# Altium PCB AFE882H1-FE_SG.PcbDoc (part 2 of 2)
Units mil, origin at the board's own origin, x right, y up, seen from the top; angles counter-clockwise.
Board outline 2755.91 x 1181.1 mil, 4 copper layers (Top Layer, Int1 (GND), Int2 (PWR), Bottom Layer), stack 53.912 mil thick; 101 components, 57 nets, 291 pads, 95 vias.
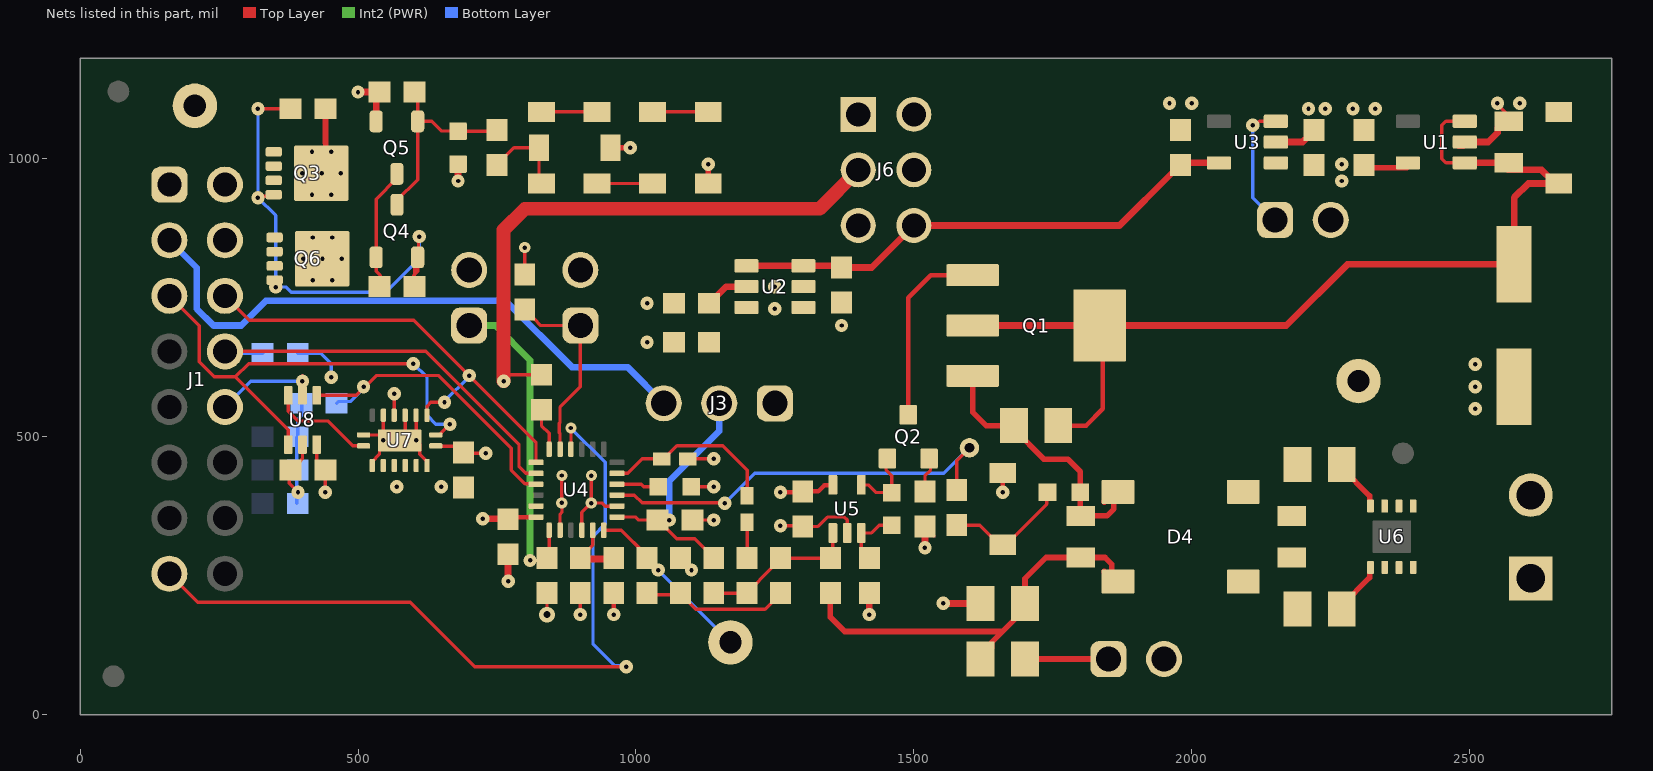
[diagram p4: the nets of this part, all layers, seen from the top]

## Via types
v1: diameter 24, hole 8, Top Layer to Bottom Layer, tented both sides, 65 vias
v2: diameter 19.68, hole 7.87, Top Layer to Bottom Layer, 16 vias
v3: diameter 20, hole 8, Top Layer to Bottom Layer, tented both sides, 9 vias
v4: diameter 19.68, hole 7.87, Top Layer to Bottom Layer, tented both sides, 4 vias
v5: diameter 28, hole 12, Top Layer to Bottom Layer, tented both sides, 1 vias

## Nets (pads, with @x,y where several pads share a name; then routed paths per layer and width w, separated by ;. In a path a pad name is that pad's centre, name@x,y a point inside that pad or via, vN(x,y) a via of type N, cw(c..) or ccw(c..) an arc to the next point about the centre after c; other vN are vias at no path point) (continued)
GND: C2.2 C3.2 C4.2 C5.1 C6.2 C9.2 C10.2 C11.2 C12.2 C13.2 C15.2 C16.2 C18.1 C19.2 C20.2 C21.2 C22.1 C24.2 C25.2 D2.2 J1.1 J8.2 Q5.2 R3.2 R4.1 R9.1 R13.2 R20.1 TP3.1 TP4.1 U1.2 U2.1 U2.2 U3.2 U4.14 U4.16 U4.20 U5.2 U7.3 U7.4 U7.6 U7.8 U7.10 U7.11 U7.12 U7.13 U7.14 U7.15 U7.17 U8.3 | length 1649.5
  Top Layer w6: U8.3@425.59,485.71 425.59,455.7 C25.2@441.29,440 ; v1(441.29,400) 441.29,439.8 C25.2@441.5,440 C25.2@450,440 ; U7.8@510.04,503.13 538.63,503.13 U7.17@545.47,496.29 ; U7.10@525.79,448.01 525.79,455.1 538.63,467.94 538.63,486.44 v4(545.47,493.29) U7.17@545.47,496.29 ; U7.6@544.9,539.13 U7.6@545.47,538.56 U7.17@545.47,496.29 ; U7.17@575,493.29 584.84,503.13 U7.4@584.84,538.56 ; U7.3@604.53,538.56 v4(604.53,493.29) 611.37,486.44 611.37,467.94 624.21,455.1 U7.15@624.21,448.01 ; R3.2@800,791.5 v3(800,840) ; v5(840,180) C12.2@840,222.44 ; U4.14@863.46,331.72 863.46,360.14 866.93,363.61 866.93,380.67 v3(866.6,381) ; v3@863.46,377.85 v3(866.6,381) ; v3(866.93,430.19) 866.6,429.86 v3(866.6,381) ; v1(900,180) C11.2@900,218.5 900,217.52 C11.2@915.7,201.82 ; U4.16@902.83,331.72 902.83,363.65 v3@919.18,380 ; v3(919.74,429.89) 919.7,429.85 v3(919.7,380.52) ; v3@920,380 v3@919.18,380 ; U4.20@965.82,375.03 945.02,375.03 942.22,377.83 939.52,380.52 v3(919.7,380.52) ; C6.2@1068.51,740 C6.2@1075.28,733.23 ; C2.2@1070.47,663.3 C2.2@1070.47,670 ; C15.2@1080,281.5 1100,261.5 v1(1100,260) ; C18.1@1093.62,460 v1(1140,460) ; C13.2@1101.49,350 v1(1140,350) ; C16.2@1103.41,408.09 1101.5,410 v1(1140,410) ; v1(1260,340) 1298.51,340 C9.2@1300,338.51 1327.7,338.51 1344.53,355.34 1374.87,355.34 1380,350.21 U5.2@1380,326.69 ; R9.1@1520,338.5 1520,337.52 R9.1@1535.7,321.82 ; U1.2@2479.68,1020.88 U1.2@2489.52,1020.88 ; v1@2556.6,1090.97 C5.1@2568.24,1079.33 ; v3@919.18,380 v3(919.7,380.52)
  Top Layer w12: v1(500,1120) R20.1@538.5,1120 ; Q5.2@532.6,1067.24 532.6,1112.6 R20.1@539.25,1119.25 ; v1(680,960) C22.1@680,990.47 ; v1(770,240) C10.2@770,288.5 ; v1(1420,180) R4.1@1420,216.54 ; v1(1520,300) R9.1@1520,338.5 ; v1(1553.21,200) R13.2@1602.91,200 ; U3.2@2151.18,1030 2199.49,1030 2209.49,1040 C19.2@2230,1040 ; U1.2@2491.18,1030 2533.5,1030 2550.41,1046.91 2550.41,1055.68 2554.72,1060 C5.1@2570,1060
  other v1: 570,410 650,410 2510,550 2510,590 2510,630 1020,670 1370,700 1250,730 1020,740 1250,770 2210,1090 2240,1090 2290,1090 2330,1090 1960,1100 2000,1100 2550,1100 2590,1100
ID0: J1.5 U7.1 U8.1 | length 893.4
  Top Layer w6: J1.5@160.52,753.39 214.65,699.27 214.65,634.39 241.52,607.52 279.53,607.52 ; U8.1@374.41,485.71 374.41,512.63 279.53,607.52 ; v1(599.61,631.33) 303.34,631.33 279.53,607.52 ; U7.1@639.96,503.13 647.05,503.13 650,506.08 650,507.25 v1(665.36,522.62)
  Bottom Layer w6: v1(599.61,631.33) 624.21,606.72 624.21,538.56 640.16,522.62 v1(665.36,522.62)
IOVDD: C10.1 C24.1 C25.1 J6.3 R8.2 R10.2 R12.2 R15.2 R16.2 R21.2 U4.12 U7.5 U7.16 U8.2 | length 1635.4
  Top Layer w6: C25.1@378.5,440 376.22,437.71 376.22,415.81 v1(392.03,400) ; C25.1@380,440.51 395.19,455.7 395.7,455.7 400,460 U8.2@400,485.71 ; U7.5@565.16,538.56 v1(565.16,577.01) ; U7.16@639.96,483.44 640.42,482.99 C24.1@690,482.99 ; C24.1@690,471.5 691.5,470 v1(730,470) ; v1(724.17,352.59) v1@725.26,351.5 ; v1(762.1,600) 773.6,611.5 R8.2@830,611.5
  Top Layer w8: C10.1@770,360 774.66,355.34 U4.12@820.15,355.34
  Top Layer w12: v1(724.17,352.59) 767.41,352.59 C10.1@770,350
  Top Layer w25: v1(762.1,600) 762.1,872.1 800,910 1330,910 J6.3@1400,980
  Bottom Layer w6: R16.2@390,380 390,397.97 v1(392.03,400) ; v1@390,400 390,498.5 R21.2@391.5,500 391.5,531.55 398.5,538.56 R12.2@398.5,560 ; R10.2@391.5,650 433.06,650 451.73,631.33 v1(451.73,606.72)
LOOP+: C1.2 C8.2 D4.1 Q1.3 R2.2 | length 506.1
  Top Layer w10: Q1.3@1605.83,609.45 1605.83,544.17 1630,520 R2.2@1670,520 ; R2.2@1680,520 1680,513.5 1734.07,459.43 1777.02,459.43 1799.53,436.92 C1.2@1799.53,400 1799.53,367.87 C8.2@1805,362.4 ; C8.2@1800,357.4 1847.4,357.4 1859.91,369.91 1859.91,393.22 D4.1@1867.4,400.71 1859.53,400.71 1842.87,384.05 D4.1@1842.87,382.4
LOOP-: C8.1 D4.4 R13.1 R14.1 R23.1 | length 790.3
  Top Layer w10: R14.1@1350,218.5 1350,175.17 1375.72,149.45 1659.45,149.45 ; R23.1@1620,100 1640,120 1640,130 1659.45,149.45 ; R13.1@1711.18,205.9 R13.1@1717.09,200 ; R13.1@1720,210 R13.1@1720,213.74 ; D4.4@1842.87,257.6 1842.87,255.95 1856.5,242.32 D4.4@1860,242.32 ; D4.4@1867.4,239.29 1856.41,250.28 1856.41,270.09 1843.9,282.6 C8.1@1800,282.6 1738.07,282.6 1700,244.53 R13.1@1700,200 1680,180 1680,170 1659.45,149.45
MOD_IN: R1.1 TP1.1 U4.21 | length 767.3
  Top Layer w6: U4.21@965.82,394.71 997.36,394.71 1011.07,381 1159,381 v1(1160,380) ; R1.1@1577.06,403.89 1577.06,457.06 TP1.1@1600,480
  Bottom Layer w6: v1(1160,380) 1214.08,434.08 1554.08,434.08 TP1.1@1600,480
NetC1_1: C1.1 D1.2 R1.2 | length 227.1
  Top Layer w6: R1.2@1577.06,340.9 1618.63,340.9 1649.53,310 D1.2@1660,310 ; D1.2@1660,305.53 1666,305.53 1739.24,378.77 1739.24,398.76 C1.1@1740.47,400
NetC2_1: C2.1 J3.1 U2.6
NetC5_2: C5.2 C21.1 D2.1 Q1.2 Q1.4 R2.1 U1.1 U1.3 | length 1771.9
  Top Layer w6: U1.1@2491.18,992.6 2457.4,992.6 2450,1000 2450,1060 2457.4,1067.4 U1.3@2491.18,1067.4
  Top Layer w8: R2.1@1760,520 1810,520 1840,550 1840,690 Q1.4@1850,700
  Top Layer w12: Q1.2@1605.83,700 Q1.4@1830,700 ; Q1.4@1834.17,700 1850,700 2170,700 2280,810 C21.1@2570,810 ; U1.1@2500.51,992.6 C5.2@2570,992.6 ; C5.2@2567.4,982.6 2570,980 2629.53,980 D2.1@2649.53,960 ; C21.1@2580,810.24 2580,930 2605.53,955.53 2649.53,955.53 D2.1@2660,955.53
NetC6_1: C6.1 U2.5 | length 101.8
  Top Layer w6: C6.1@1125.27,754.63 1135.7,744.2 1136.19,743.71 C6.1@1139.32,740.58 ; C6.1@1130.51,740 C6.1@1131.5,740
  Top Layer w12: C6.1@1131.5,740 1132.48,740 1162.48,770 U2.5@1200,770
NetC7_1: C7.1 R4.2 U5.3 | length 111.3
  Top Layer w6: R4.2@1420,281.5 1405.59,295.91 U5.3@1405.59,326.69 1423.9,326.69 1437.68,340.47 C7.1@1460,340.47
NetC7_2: C7.2 Q2.1 U5.4 | length 126.4
  Top Layer w6: U5.4@1405.59,413.31 1405.86,413.04 1418.95,413.04 1432.46,399.53 C7.2@1460,399.53 1460,430 1450,440 1450,458.03 Q2.1@1452.6,460.63
NetC11_1: C11.1 R22.2 U4.17 | length 107.5
  Top Layer w6: C11.1@900,281.49 C11.1@901.49,280 ; C11.1@910,290 910,292.48 922.51,304.99 U4.17@922.51,331.72
  Top Layer w12: C11.1@901.49,280 R22.2@960,280
NetC14_1: C14.1 D4.2 FB2.1
NetC14_2: C14.2 D4.3 FB1.1
NetC15_1: C15.1 R6.1 R7.1 | length 273.2
  Top Layer w6: R6.1@1020,215.48 1076.98,215.48 C15.1@1080,218.5 ; R6.1@1024.09,228.83 R6.1@1030.08,228.83 ; C15.1@1080,219.49 C15.1@1080,218.5 ; R7.1@1260,218.5 1260,217.52 1232.25,189.77 1107.75,189.77 1080,217.52 C15.1@1080,218.5
NetC16_1: C16.1 U4.22 | length 76.5
  Top Layer w6: U4.22@965.82,414.4 1009.37,414.4 1013.77,410 C16.1@1040.47,410
NetC17_1: C17.1 R11.1 | length 58.5
  Top Layer w6: R11.1@1200,281.5 C17.1@1200,340
NetC17_2: C17.2 C18.2 U4.23 | length 319
  Top Layer w6: U4.23@965.82,434.08 985.57,434.08 1011.49,460 C18.2@1046.38,460 1050.31,460 1073.76,483.44 1156.56,483.44 1200,440 C17.2@1200,393.62
NetC22_2: C22.2 Q4.3 Q5.1 R19.1 R20.2 | length 366.2
  Top Layer w6: Q4.3@570,920 570,925.12 607.4,962.52 Q5.1@607.4,1067.24 632.76,1067.24 650,1050 C22.2@680,1050 ; R20.2@601.5,1120 607.4,1114.09 607.4,1072.6 Q5.1@610,1070 ; C22.2@680,1049.53 749.53,1049.53 R19.1@750,1050
NetD3_1: D3.1 D5.2 | length 101.9
  Top Layer w6: D5.2@1030,1084.47 1125.53,1084.47 D3.1@1130,1080
NetD5_1: D5.1 D6.2 | length 112.3
  Top Layer w6: D6.2@930,955.53 D5.1@1030,955.53 1034.47,955.53 D5.1@1040,950
NetD6_1: D6.1 D7.2 | length 102.3
  Top Layer w6: D7.2@830,1084.47 924.47,1084.47 D6.1@930,1090
NetD7_1: D7.1 D8.2 R19.2 | length 161
  Top Layer w6: R19.2@750,988.5 750,989.49 780.51,1020 D8.2@825.53,1020 825.53,954.47 D7.1@830,950
NetFB1_2: FB1.2 J2.1 U6.1 U6.2 U6.3 U6.4 | length 129.9
  Top Layer w10: FB1.2@2270,190 2270,196.5 2320,246.5 U6.1@2320,260 ; J2.1@2584.32,270.68 J2.1@2609.08,245.92 ; J2.1@2610,245 J2.1@2609.08,245.92 ; J2.1@2611.9,245.92 J2.1@2609.08,245.92
NetFB2_2: FB2.2 J2.2 U6.5 U6.6 U6.7 U6.8 | length 102.3
  Top Layer w10: FB2.2@2270,450 2270,443.5 2320,393.5 U6.8@2320,380 ; J2.2@2602.73,387.73 J2.2@2610,395 J2.2@2609.08,395.92
NetJ4_1: J4.1 U3.3 | length 216.7
  Top Layer w6: v1(2110,1060) 2114.43,1060 2121.83,1067.4 U3.3@2151.18,1067.4
  Bottom Layer w6: v1(2110,1060) 2110,930 J4.1@2140,900
NetJ8_1: J8.1 R23.2 | length 150
  Top Layer w10: R23.2@1700,100 J8.1@1850,100
NetQ1_1: Q1.1 Q2.3 | length 342.6
  Top Layer w8: Q2.3@1490,540 1490,750 1530.55,790.55 Q1.1@1605.83,790.55
NetQ2_2: Q2.2 R9.2 | length 65.8
  Top Layer w6: R9.2@1520,401.5 1520,430 1530,440 Q2.2@1530,458.03
  Top Layer w8: R9.2@1520,400 R9.2@1520,401.5 ; Q2.2@1527.4,460.63 Q2.2@1530,458.03
NetQ3_4: Q3.4 Q4.2 Q6.4 R17.1 R18.2 | length 879.9
  Top Layer w6: v1(320,930) 322.77,932.77 345.54,932.77 Q3.4@348.31,935.53 ; v1(320,1090) R17.1@378.5,1090 ; Q6.4@349.96,781.61 352,779.57 v1(352,769.21) ; 600,790 601.5,791.5 ; R18.2@601.5,770 601.5,791.5 ; v1(610,860) 608.7,858.7 608.7,824.06 Q4.2@607.4,822.76 Q4.2@607.4,807.4 ; 601.5,791.5 607.4,797.4 Q4.2@607.4,807.4 ; 601.5,791.5 601.5,806.29 602.61,807.4 Q4.2@607.4,807.4
  Bottom Layer w6: v1(320,1090) v1(320,930) 352,898 v1(352,769.21) 370.79,769.21 380,760 550,760 610,820 v1(610,860)
NetQ4_1: Q4.1 Q5.3 R18.1 | length 215.1
  Top Layer w6: Q4.1@530,830 532.6,832.6 532.6,927.48 570,964.88 Q5.3@570,972.76 ; Q4.1@532.6,822.76 532.6,797.4 540,790 R18.1@540,770
NetR5_2: R5.2 R7.2 R11.2 R14.2 U5.1 | length 287
  Top Layer w6: R5.2@1140,218.5 R11.2@1200,218.5 1200,219.49 1244.3,263.79 1244.3,265.8 R7.2@1260,281.5 1348.5,281.5 1350,280 1354.41,284.41 U5.1@1354.41,326.69
NetR6_2: R6.2 TP2.1 U4.18 | length 321.7
  Top Layer w6: U4.18@942.2,331.72 973.71,331.72 1015.43,290 R6.2@1030,290 ; R6.2@1020,284.52 1040,264.52 v1(1040,260)
  Bottom Layer w6: v1(1040,260) TP2.1@1170,130
NetR8_1: R8.1 U4.6 | length 76.8
  Top Layer w6: R8.1@830,548.5 830,520 843.77,506.23 U4.6@843.77,477.39
NetU4_11: U4.11
NetU7_9: U7.9 U8.6 | length 189.9
  Top Layer w6: U8.6@374.41,574.29 374.41,545.88 392.03,528.26 445.84,528.26 490.66,483.44 U7.9@510.04,483.44
PVDD: C9.1 D1.1 J6.4 J7.2 R22.1 U5.5 | length 187
  Top Layer w8: v1(960,180) R22.1@960,218.5 ; v1(1260,400) 1298.5,400 C9.1@1300,401.5 1327.95,401.5 1339.22,412.77 1353.87,412.77 U5.5@1354.41,413.31 ; v1(1660,400) D1.1@1660,434.47 D1.1@1670,444.47
REF_EN: J7.1 R3.1 U4.5 | length 351.1
  Top Layer w6: R3.1@800,728.5 800,727.52 815.7,711.82 816.69,711.82 828.5,700 J7.1@900,700 900,590 863.46,553.46 863.46,525.42 862.27,524.24 862.27,506.94 863.46,505.76 U4.5@863.46,477.39
RTS: J1.15 U4.4 | length 1429.9
  Top Layer w6: J1.15@160.52,253.39 211.96,201.96 593.89,201.96 710,85.85 v1(982.66,85.85) ; U4.4@883.14,477.39 v3(883.14,515.59)
  Bottom Layer w6: v3(883.14,515.59) 944.61,454.12 944.61,342.88 922.87,321.14 922.87,126.5 961.66,87.72 980.79,87.72 v1(982.66,85.85)
SCLK: J1.6 U4.7 U7.2 | length 822.2
  Top Layer w6: J1.6@260.52,753.39 304.63,709.28 600.72,709.28 820.15,489.85 U4.7@820.15,453.77 ; U7.2@624.21,538.56 624.21,555.03 630.83,561.65 v1(655.6,561.65)
  Bottom Layer w6: v1(655.6,561.65) 655.6,563.63 700,608.02 v1(700,610)
SDI: J1.8 R10.1 U4.8 | length 743
  Top Layer w6: J1.8@260.52,653.39 621.64,653.39 789.76,485.26 789.76,445.74 801.43,434.08 U4.8@820.15,434.08
  Bottom Layer w6: J1.8@260.52,653.39 263.92,650 R10.1@328.5,650
SDO: J1.10 U8.5 | length 201
  Top Layer w6: J1.10@260,560 J1.10@267.13,560 ; U8.5@400,574.29 v1(400,600) v1@400,609.33
  Bottom Layer w6: J1.10@260.52,553.39 307.13,600 v1(400,600)
SDO_DAC: R12.1 U4.9 U8.4 | length 576.2
  Top Layer w6: U8.4@425.59,574.29 497.01,574.29 532.72,610 645.07,610 775.89,479.18 775.89,440 800.29,415.59 818.95,415.59 U4.9@820.15,414.4
  Bottom Layer w6: R12.1@461.5,560 464.88,563.39 486.67,563.39 510,586.72 v1(510,590)
VDD-1V8: C3.1 C4.1 J5.2 J6.6 Q6.5 Q6.6 Q6.7 Q6.8 Q6.9@435.59,820 U2.3 U2.4 U3.5 | length 944.1
  Top Layer w12: U2.4@1198.82,807.4 U2.3@1297.4,807.4 ; U2.3@1301.18,807.4 C3.1@1362.6,807.4 ; C3.1@1370,804.33 1424.33,804.33 1490,870 J6.6@1510,870 ; J6.6@1500,880 1870,880 1964.82,974.82 1967.3,974.82 1980,987.52 1980,990 1982.6,992.6 U3.5@2048.82,992.6
  Int2 (PWR) w12: J6.6@1490,890 J6.6@1510,890
  other v2: 418.9,781.61 453.39,781.61 401.65,820 436.14,820 418.9,858.39 453.39,858.39
  other v4: 470.63,820
VDD-1V8-SW: J1.4 J6.5 Q6.1 Q6.2 Q6.3 | length 6.8
  Int2 (PWR) w12: J1.4@260,860 260,853.92 J1.4@260.52,853.39
VDD-3V3: C19.1 C20.1 D3.2 D8.1 J4.2 J6.2 Q3.5 Q3.6 Q3.7 Q3.8 Q3.9@433.94,973.92 R17.2 U1.5 U3.1 | length 238.5
  Top Layer w10: R17.2@441.5,1090 441.5,1028.5 442.09,1027.91 Q3.9@442.09,1017.91 ; D8.1@954.47,1020 v1(990,1020) ; D3.2@1130,955.53 v1(1130,990) ; C20.1@2301.5,980 C20.1@2306.81,985.31 ; C20.1@2310,988.5 C20.1@2306.81,985.31 ; U1.5@2387.16,983.48 2308.64,983.48 C20.1@2306.81,985.31
  Int2 (PWR) w10: v2@450,1010 450,1010.57 v2(451.73,1012.3)
  other v1: 2270,960 2270,990
  other v2: 417.24,935.53 451.73,935.53 400,973.92 434.49,973.92 417.24,1012.3
  other v4: 468.98,973.92
VDD-3V3-SW: J1.2 J6.1 Q3.1 Q3.2 Q3.3 | length 7.1
  Int2 (PWR) w12: J1.2@260,960 J1.2@267.13,960
VDD_int: C12.1 J5.1 U4.13 | length 579.3
  Top Layer w6: v1(809.49,277.34) 839.78,277.34 C12.1@840,277.56 ; U4.13@843.77,331.72 843.77,287.06 C12.1@849.76,281.07
  Int2 (PWR) w12: J5.1@700,700 747.1,700 809.49,637.61 v1(809.49,277.34)
VREF_AFE: C13.1 J3.2 R5.1 U4.19 | length 473.1
  Top Layer w6: U4.19@965.82,355.34 999.66,355.34 1005,350 C13.1@1038.5,350 C13.1@1039.49,350 ; v1(1060,350) C13.1@1039.49,350 ; R5.1@1140,281.5 1140,282.48 1106.24,316.24 1073.25,316.24 C13.1@1039.49,350
  Bottom Layer w12: v1(1060,350) 1060,420 1150,510 J3.2@1150,560
VREF_EXT: J1.3 J3.3 | length 1101.6
  Top Layer w6: J1.3@160.52,853.39 J1.3@171,853.39
  Bottom Layer w12: J1.3@160.52,853.39 210,803.92 210,730 240,700 290,700 334.48,744.48 765.52,744.48 884.87,625.13 984.87,625.13 J3.3@1050,560
pads on no net: FID1.1 FID2.1 FID3.1 J1.7 J1.9 LBL1.0 Q3.9@400,947.83 Q3.9@400,1000 Q3.9@421.24,973.92 Q3.9@434.49,947.83 Q3.9@434.49,1000 Q3.9@454.61,935.53 Q3.9@454.61,961.12 Q3.9@454.61,986.71 Q3.9@454.61,1012.3 Q6.9@401.65,793.92 Q6.9@401.65,846.08 Q6.9@422.89,820 Q6.9@436.14,793.92 Q6.9@436.14,846.08 Q6.9@456.26,781.61 Q6.9@456.26,807.2 Q6.9@456.26,832.8 Q6.9@456.26,858.39 SH-J1.0 SH-J2.0 SH-J3.0 SH-J4.0 SH-J5.0 SH-J6.0 U1.4 U3.4 U6.9 U7.7
copper on no net:
  other v2: 2360,300.31 2335.39,320 2384.61,320 2360,339.68

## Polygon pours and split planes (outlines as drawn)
GND on Top Layer "TOP_LAYER_GND_P053" (solid, remove dead copper, pour order 53): 2620,660 2620,520 2610,510 2500,510 2480,530 2480,650 2500,670 2610,670
NetFB2_2 on Top Layer "TOP_LAYER_NETFB2_2_P051" (solid, remove dead copper, pour order 51): 2320,350 2650,350 2660,360 2660,440 2650,450 2480,450 2420,390 2320,390 2310,380 2310,360
NetFB1_2 on Top Layer "TOP_LAYER_NETFB1_2_P050" (solid, remove dead copper, pour order 50): 2320,290 2650,290 2660,280 2660,200 2650,190 2480,190 2420,250 2320,250 2310,260 2310,280
GND on Top Layer "TOP_LAYER_GND_P049" (solid, remove dead copper, pour order 49): 1400,760 1400,690 1390,680 1300,680 1300,770 1390,770
GND on Top Layer "TOP_LAYER_GND_P048" (solid, remove dead copper, pour order 48): 710,430 620,430 620,390 710,390 720,400 720,420
GND on Top Layer "TOP_LAYER_GND_P047" (solid, remove dead copper, pour order 47): 520,481.5 630,481.5 630,390 540,390 520,410
NetC2_1 on Top Layer "TOP_LAYER_NETC2_1_P041" (solid, remove dead copper, pour order 41): 1180,750 1220,750 1230,740 1230,710 1310,630 1310,520 1300,510 1210,510 1200,520 1200,590 1150,640 1120,640 1110,650 1110,690 1120,700 1160,700 1170,710 1170,740
VDD-1V8-SW on Top Layer "TOP_LAYER_VDD-1V8-SW_P040" (solid, remove dead copper, pour order 40): 370.23,883.28 370.23,813.28 370.23,800 230,800 220.23,809.77 220.23,883.28 230.23,893.28 360.23,893.28
VDD-3V3-SW on Top Layer "TOP_LAYER_VDD-3V3-SW_P038" (solid, remove dead copper, pour order 38): 370,1020 370,950 370,910 360,900 230,900 220,910 220,1020 230,1030 360,1030
VDD-3V3 on Top Layer "TOP_LAYER_VDD-3V3_P037" (solid, remove dead copper, pour order 37): 2130,1010 2410,1010 2420,1000 2420,960 2410,950 2320,950 2310,940 2310,860 2300,850 2210,850 2200,860 2200,940 2190,950 2130,950 2120,960 2120,1000
GND on Top Layer "TOP_LAYER_GND_P036" (solid, remove dead copper, pour order 36): 790,520 990,520 990,310 980,300 790,300
NetC5_2 on Top Layer "TOP_LAYER_NETC5_2_P035" (solid, remove dead copper, pour order 35): 1550,820 2100,820 2120,800 2120,580 2100,560 1550,560
NetC14_2 on Top Layer "TOP_LAYER_NETC14_2_P034" (solid, remove dead copper, pour order 34): 2060,290 2200,290 2210,280 2210,130 2200,120 2140,120 2050,210 2050,280
NetC14_1 on Top Layer "TOP_LAYER_NETC14_1_P033" (solid, remove dead copper, pour order 33): 2210,510 2210,360 2200,350 2060,350 2050,360 2050,430 2140,520 2200,520
GND on Top Layer "TOP_LAYER_GND_P031" (solid, remove dead copper, pour order 31): 1240,790 1320,790 1330,780 1330,680 1270,680 1230,720 1230,780
GND on Top Layer "TOP_LAYER_GND_P030" (solid, remove dead copper, pour order 30): 1010,770 1090,770 1100,760 1100,650 1090,640 1010,640 1000,650 1000,760
GND on Top Layer "TOP_LAYER_GND_P021" (solid, pour order 21): 2530,1110 2530,1030 2690,1030 2700,1040 2700,1110 2690,1120 2540,1120
GND on Top Layer "TOP_LAYER_GND_P022" (solid, pour order 22): 2270,1100 2270,1030 2280,1020 2340,1020 2350,1030 2350,1100 2340,1110 2280,1110
GND on Top Layer "TOP_LAYER_GND_P027" (solid, pour order 27): 2190,1020 1950,1020 1940,1030 1940,1110 1950,1120 2020,1120 2030,1110 2030,1060 2050,1040 2190,1040
GND on Top Layer "TOP_LAYER_GND_P026" (solid, pour order 26): 2260,1110 2260,1030 2250,1020 2190,1020 2180,1030 2180,1100 2190,1110
VDD-3V3 on Int2 (PWR) "INT2_(PWR)_VDD-3V3_P052" (solid, remove dead copper, pour order 52): 2280,1010 1920,1010 1890,1040 1890,1130 1870,1150 1470,1150 1470,1020 1760,1020 1780,1000 1780,960 1800,940 2280,940 2290,950 2290,1000
VDD-1V8-SW on Int2 (PWR) "INT2_(PWR)_VDD-1V8-SW_P046" (solid, remove dead copper, pour order 46): 1420,890 1420,860 1400,840 870,840 760,730 260,730 220,770 220,890 230,900 320,900 340,880 340,820 370,790 760,790 880,910 1400,910
VDD-1V8 on Int2 (PWR) "INT2_(PWR)_VDD-1V8_P045" (solid, remove dead copper, pour order 45): 380,880 380,790 760,790 880,910 1430,910 1450,890 1450,860 1470,840 1520,840 1540,860 1540,930 1520,950 540,950 470,880
VDD-3V3 on Int2 (PWR) "INT2_(PWR)_VDD-3V3_P044" (solid, remove dead copper, pour order 44): 380,1030 380,930 400,910 490,910 530,950 1550,950 1550,1140 1540,1150 1460,1150 1450,1140 1450,1050 400,1050
VDD-3V3-SW on Int2 (PWR) "INT2_(PWR)_VDD-3V3-SW_P043" (solid, remove dead copper, pour order 43): 230,920 290,920 340,970 340,1020 370,1050 1430,1050 1440,1060 1440,1140 1430,1150 260,1150 220,1110 220,930
PVDD on Int2 (PWR) "INT2_(PWR)_PVDD_P023" (solid, remove dead copper, pour order 23): 1670,840 1670,990 1650,1010 1480,1010 1470,1000 1470,960 1480,950 1540,950 1560,930 1560,860 1540,840 880,840 860,820 860,150 1448.18,150 1670,377.83
IOVDD on Int2 (PWR) "INT2_(PWR)_IOVDD_P024" (solid, remove dead copper, pour order 24): 310.52,603.39 357.13,650 739.73,650 780,609.73 780,352 738.2,310.2 352,310.2 310.52,351.67
GND on Int1 (GND) "INT1_(GND)_GND_P002" (solid, remove dead copper, pour order 2): 0,1181.1 0,0 2755.91,0 2755.91,1181.1

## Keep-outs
Keep-Out Layer:
  text ".Layer_Name" at 577,-858.49 h60

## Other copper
Top Layer:
  text ".Layer_Name" at 577,-858.49 h60
Bottom Layer:
  text ".Layer_Name" at 577,-858.49 h60

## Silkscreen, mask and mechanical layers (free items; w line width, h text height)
Top Overlay:
  text "3.3V" at 1583.06,1111 h30
  text "IOVDD" at 1196,966 h30
  text "PVDD" at 1576,966 h30
  text "1.8V" at 1583.06,856 h30
  text "1.8_En" at 2116,791 h30
  text "FT-EVP-AFE88x_E2" at 1920,720 h60
  text "ref_EN" at 979.39,667.5 h30 r90
  text "VDD" at 626,626 h30
  text "Vref" at 1176,606 h30
  text ".Layer_Name" at 577,-858.49 h60
Bottom Overlay:
  text ".Layer_Name" at 577,-858.49 h60
Top Paste:
  text ".Layer_Name" at 577,-858.49 h60
Bottom Paste:
  text ".Layer_Name" at 577,-858.49 h60
Top Solder:
  text ".Layer_Name" at 577,-858.49 h60
  text ".Layer_Name" at 577,-858.49 h60
Bottom Solder:
  text ".Layer_Name" at 577,-858.49 h60
Drill Guide:
  text ".Layer_Name" at 577,-858.49 h60
M1 Board Outline:
  the board outline again, w7
  text ".Layer_Name" at 577,-858.49 h60
M2 Board Dimensions:
  rectangle: 0,-275 125,-150
  rectangle: 125,-400 500,-275
  lines w7: 0,-275 1000,-275 ; 125,-400 125,-150 ; 250,-400 250,-150 ; 500,-400 500,-150 ; 750,-400 750,-150 ; 0,-400 1000,-400 1000,-150 0,-150 0,-400
  text ".Layer_Name" at 577,-858.49 h60
M3 3D STEP Top:
  text ".Layer_Name" at 577,-858.49 h60
M4 3D STEP Bottom:
  text ".Layer_Name" at 577,-858.49 h60
M5 Assembly Top:
  lines w10: -292,-930.17 6308,-930.17 ; -292,-726.83 6310,-726.83 ; -292,-523.5 -292,-1133.5 3713,-1133.5 6310,-1133.5 6310,-523.5 -291.5,-523.5 -291.5,-1133.5 1284,-1133.5 ; 2173,-1133.5 2173,-523.5 ; 3440,-726.83 3440,-523.5 ; 4280,-726.83 4280,-523.5 ; 4902,-1140 4902,-937.17
  text "COMPONENTS MARKED 'DNP' SHOULD NOT BE POPULATED." at 1153.5,-318.5 h60
  text "ASSEMBLY VARIANT:" at 1153,-434 h60
  text ".VariantName" at 2189,-434 h60
  text "PCB VIEWED FROM TOP SIDE" at -228.5,-655.67 h60
  text "BOARD #:" at 2248,-655.67 h60
  text ".PRJ_Number" at 2793.5,-655.67 h60
  text "REV:" at 3638,-655.67 h60
  text ".PCB_Rev" at 3929.5,-655.67 h60
  text "SVN REV:" at 4476,-655.67 h60
  text ".VersionControl_RevNumber" at 4982,-655.67 h60
  text "TID #:" at 2248,-859 h60
  text ".TID" at 2793.5,-859 h60
  text "PLOT NAME =" at -228.5,-1064.34 h60
  text ".plot_File_Name" at 577,-1064.34 h60
  text "GENERATED    :" at 2250,-1064.34 h60
  text ".Print_Date" at 3119.5,-1064.34 h60
  text ".Print_Time" at 3848.5,-1064.34 h60
  text "TEXAS INSTRUMENTS" at 5113,-1064.34 h60
M6 Assembly Bottom:
  lines w10: -292.5,-727.33 6309.5,-727.33 ; -290.5,-930.67 6309.5,-930.67 ; 1115.5,-1140.5 1115.5,-937.67 ; 1737.5,-727.33 1737.5,-524 ; 2577.5,-727.33 2577.5,-524 ; 3844.5,-1134 3844.5,-524 ; 4733.5,-1134 6309,-1134 6309,-524 -292.5,-524 -292.5,-1134 2304.5,-1134 6309.5,-1134 6309.5,-524
  text "COMPONENTS MARKED 'DNP' SHOULD NOT BE POPULATED." at 6102,-318 h60
  text ".VariantName" at 5058,-434 h60
  text "ASSEMBLY VARIANT:" at 6097,-434 h60
  text ".VersionControl_RevNumber" at 1035.5,-656.17 h60
  text "SVN REV:" at 1541.5,-656.17 h60
  text ".PCB_Rev" at 2088,-656.17 h60
  text "REV:" at 2379.5,-656.17 h60
  text ".PRJ_Number" at 3224,-656.17 h60
  text "BOARD #:" at 3769.5,-656.17 h60
  text "PCB VIEWED FROM BOTTOM SIDE" at 6246,-656.17 h60
  text ".TID" at 3224,-859.5 h60
  text "TID #:" at 3769.5,-859.5 h60
  text "TEXAS INSTRUMENTS" at 904.5,-1064.84 h60
  text ".Print_Time" at 2169,-1064.84 h60
  text ".Print_Date" at 2898,-1064.84 h60
  text "GENERATED    :" at 3767.5,-1064.84 h60
  text ".plot_File_Name" at 5440.5,-1064.84 h60
  text "PLOT NAME =" at 6246,-1064.84 h60
M9 Title Sheet:
  drawing of 57 lines, arcs and shapes, not listed
  text "1" at 739.84,8036.5 h70
  text "2" at 3235.5,8036.5 h70
  text "3" at 5724.84,8036.5 h70
  text "4" at 8231.51,8036.5 h70
  text "5" at 10730.5,8036.5 h70
  text "6" at 13235.5,8036.5 h70
  text "A" at -416.5,6893.5 h70
  text "A" at 14383.5,6893.5 h70
  text "B" at -416.5,4513.5 h70
  text "B" at 14383.5,4513.5 h70
  text "C" at -416.5,2138.5 h70
  text "C" at 14383.5,2138.5 h70
  text "PROJECT TITLE:" at 11343.5,277.5 h45
  text ".PRJ_Title" at 11393.5,144.17 h70
  text "DESIGNED FOR:" at 11343.5,-23.5 h45
  text ".PRJ_Customer" at 11393.5,-163.5 h70
  text "D" at -416.5,-231.5 h70
  text "D" at 14383.5,-231.5 h70
  text "FILE NAME:" at 11343.5,-323.5 h45
  text ".PCB_File_Name_No_Path" at 11393.5,-443.5 h70
  text "Texas Instruments (TI) and/or its licensors do not warrant the accuracy or completeness of this specification" at 6374,-605.34 h45
  text "ENGINEER:" at 11343.5,-613.5 h45
  text "LAYOUT BY:" at 12848.5,-613.5 h45
  text "or any information contained therein. TI and/or its licensors do not warrant that this design will meet" at 6329.01,-718 h45
  text ".PRJ_Engineer" at 11393.5,-768.49 h70
  text ".PCB_Layout" at 12899,-768.49 h70
  text "the specifications, will be suitable for your application or fit for any particular purpose, or will operate in" at 6329.01,-830.67 h45
  text ".Layer_Name" at 577,-858.49 h60
  text "ALTIUM DESIGNER VERSION:" at 12848.5,-923.5 h45
  text "an implementation. TI and/or its licensors do not warrant that the design is production worthy. You should" at 6329.01,-943.33 h45
  text "completely validate and test your design implementation to confirm the system functionality for your application." at 6374,-1056 h45
  text ".print_Scale" at 11393.5,-1056.83 h70
  text ".Application_BuildNumber" at 12899,-1056.83 h70
  text "1" at 739.84,-1263.5 h70
  text "2" at 3235.5,-1263.5 h70
  text "3" at 5724.84,-1263.5 h70
  text "4" at 8231.51,-1263.5 h70
  text "5" at 10730.5,-1263.5 h70
  text "6" at 13235.5,-1263.5 h70
M10 Fab Notes:
  drawing of 187 lines, arcs and shapes, not listed
  text "DESIGN INFORMATION" at 12382.02,6356.17 h60
  text "MIN. TRACK WIDTH:" at 11737.46,6224.05 h60
  text "8" at 12833.7,6224.05 h60
  text "MIL" at 12988.46,6224.05 h60
  text "7.874" at 12667.32,6102.36 h60
  text "MIN. CLEARANCE:" at 11737.46,6099.92 h60
  text "MIL" at 12988.46,6099.92 h60
  text "MIN. VIA PAD SIZE:" at 11737.46,5975.8 h60
  text "24" at 12803.71,5975.8 h60
  text "MIL" at 12988.46,5975.8 h60
  text "0.05mm (2MIL)" at 12432.46,5845.9 h60
  text "MINIMUM ANNULAR RING" at 11408.23,5837.67 h60
  text "EXTERNAL" at 13140.46,5837.67 h60
  text "PER" at 11608.23,5727.55 h60
  text "IPC-D-275 CLASS 2 LEVEL C" at 11828.23,5727.54 h60
  text "MIL, HOLES" at 13316.46,5627.07 h60
  text "+/-" at 12924,5618.48 h60
  text "+/-" at 13778,5618.48 h60
  text "REGISTRATION TOLERANCES:" at 11408.23,5617.42 h60
  text "METAL" at 12608,5617.42 h60
  text "5" at 13184.2,5617.42 h60
  text "3" at 14017.2,5617.42 h60
  text "MIL" at 14133.46,5617.42 h60
  text "HOLE SIZE TOLERANCE (UNLESS OTHERWISE SPECIFIED):" at 11408.23,5519.1 h60
  text "+/-" at 13778,5516.23 h60
  text "3" at 14017.2,5515.17 h60
  text "MIL" at 14133.46,5515.17 h60
  text "MATERIAL:" at 11333.46,5377.52 h60
  text "FR-4 High Tg" at 12319.9,5249 h60
  text "X" at 12175.46,5241.01 h60
  text "FR-4" at 11754.46,5236.49 h60
  text "OTHER" at 13242.46,5236.49 h60
  text "62 MIL (1.6mm) +/-10%" at 12074.56,5093.46 h60
  text "X" at 11954.46,5091.01 h60
  text "THICKNESS:" at 11408.23,5085.24 h60
  text "OTHER" at 13359.46,5085.24 h60
  text "TOLERANCE:" at 11408.23,4946.92 h60
  text "X" at 12256.46,4946.92 h60
  text "ANSI IPC-6012 TYPE 3 CLASS 2" at 12434.48,4946.92 h60
  text "OTHER +/-" at 12434.46,4802.73 h60
  text "BOW & TWIST:" at 11408.23,4657.54 h60
  text "X" at 12256.46,4657.54 h60
  text "ANSI IPC-6012 TYPE 3 CLASS 2" at 12434.48,4657.54 h60
  text "OTHER +/-" at 12434.46,4510.85 h60
  text "DRILLING:" at 11333.46,4380.23 h60
  text "NC_DRILL FILES" at 13094.46,4275.04 h60
  text "REFERENCE:" at 11408.23,4271.1 h60
  text "X" at 12065.46,4271.01 h60
  text "AS SHOWN" at 12243.46,4271.1 h60
  text "X" at 12966.46,4271.1 h60
  text "OTHER" at 13392.46,4128.85 h60
  text "PTH COPPER THICKNESS:" at 11407.91,4125.32 h60
  text "X" at 12547.14,4125.32 h60
  text "20-30 um" at 12675.14,4125.32 h60
  text "BOARD FINISH:" at 11333.46,3977.73 h60
  text "SILKSCREEN:" at 11488.68,3867.6 h60
  text "X" at 12446.46,3867.6 h60
  text "TOP" at 12563.46,3867.6 h60
  text "X" at 12956.46,3867.6 h60
  text "BOTTOM" at 13074.46,3867.6 h60
  text "SILKSCREEN COLOR:" at 11488.68,3712.41 h60
  text "X" at 12445.46,3712.41 h60
  text "WHITE" at 12563.46,3712.41 h60
  text "OTHER" at 13074.46,3712.41 h60
  text "X" at 12576.46,3568.96 h60
  text "GREEN" at 12694.46,3568.96 h60
  text "OTHER" at 13312.46,3568.96 h60
  text "SOLDER RESIST COLOR:" at 11488.68,3562.1 h60
  text "X" at 12576.46,3414.71 h60
  text "MATTE" at 12694.46,3414.71 h60
  text "SEMI-GLOSS" at 13312,3414.07 h60
  text "IMMERSION GOLD (ENIG)" at 12394.46,3241.94 h60
  text "ENEPIG" at 13732,3234.72 h60
  text "SURFACE FINISH:" at 11333.46,3233.72 h60
  text "X" at 12216.46,3233.72 h60
  text "IMM. TIN/SILVER OR EQUIV" at 11663,3096.4 h60
  text "OTHER" at 13094.46,3092.47 h60
  text "ARRAY/PANEL:" at 11333.46,2937.09 h60
  text "CUT AND TRIM PER M1 BOARD OUTLINE" at 12394.46,2928.87 h60
  text "N.C. ROUTE" at 12394.46,2792.9 h60
  text "X" at 13082.46,2792.9 h60
  text "V. SCORE" at 13260.46,2792.9 h60
  text "CERTIFICATION:" at 11333.46,2663.77 h60
  text "MATERIALS AND WORKMANSHIP FOR ALL PCBS" at 12058.46,2663.77 h60
  text "TO MEET OR EXCEED THE REQUIREMENTS OF:" at 12058.46,2569.71 h60
  text "X" at 11695.97,2441.08 h60
  text "ANSI IPC-A-600F CLASS ->" at 11823.96,2441.08 h60
  text "X" at 13471.97,2441.08 h60
  text "2" at 13581.96,2441.08 h60
  text "1" at 13266.96,2439.58 h60
  text "3" at 13935.96,2439.58 h60
  text "X" at 12507.97,2293.39 h60
  text "RoHS" at 12635.96,2293.39 h60
  text "OTHER" at 13280.36,2293.39 h60
  text "PER ORDER" at 13677.42,2293.39 h60
  text "ALL BOARDS MUST MEET OR EXCEED UL94-V0 REQUIREMENTS." at 11361,2139.57 h60
  text "PCB MUST BEAR THE UL94V-0 UL REGISTERED MATERIAL ID NUMBER" at 11361,2023.5 h60
  text "ADDITIONAL REQUIREMENTS:" at 11333.46,1854.08 h60
  text "MICROSECTION:" at 11408.23,1746.95 h60
  text "YES" at 12313.96,1746.95 h60
  text "REQUIRED" at 13175.46,1602.62 h60
  text "BARE BOARD ELEC. TEST:" at 11408.23,1599.76 h60
  text "NONE" at 12713.96,1599.76 h60
  text "X" at 13057.46,1599.76 h60
  text "PER ORDER" at 13767.46,1599.76 h60
  text "XX MIL VIAS REQUIRE NON-CONDUCTIVE FILL AND PLANARIZE" at 11576.38,1394.82 h59
  text "XX MIL VIAS REQUIRE CONDUCTIVE FILL AND PLANARIZE" at 11584.38,1290.84 h60
  text "OUTER XX MIL TRACES REQUIRE 50 OHM SINGLE-ENDED IMPEDANCE" at 11583.39,1127.46 h58
  text "LAYER 2 & 3 (INNER LAYERS) XX MIL WIDE, XX MIL SPACE / TRACES REQUIRE 100 OHM DIFFERENTIAL IMPEDANCE" at 11575.39,891.74 h60
  text ".Layer_Name" at 577,-858.49 h60
M11 Gerber Information:
  lines w10: -292,-930.17 6308,-930.17 ; -292,-726.83 6310,-726.83 ; -292,-523.5 -292,-1133.5 3713,-1133.5 6310,-1133.5 6310,-523.5 -291.5,-523.5 -291.5,-1133.5 1284,-1133.5 ; 2173,-1133.5 2173,-523.5 ; 3440,-726.83 3440,-523.5 ; 4280,-726.83 4280,-523.5 ; 4902,-1140 4902,-937.17
  text "ALL ARTWORK VIEWED FROM TOP SIDE" at -228.5,-655.67 h60
  text "BOARD #:" at 2248,-655.67 h60
  text ".PRJ_Number" at 2793.5,-655.67 h60
  text "REV:" at 3638,-655.67 h60
  text ".PCB_Rev" at 3929.5,-655.67 h60
  text "SVN REV:" at 4476,-655.67 h60
  text ".VersionControl_RevNumber" at 4982,-655.67 h60
  text "LAYER NAME =" at -228.5,-858.49 h60
  text "TID #:" at 2248,-859 h60
  text ".TID" at 2793.5,-859 h60
  text "PLOT NAME =" at -228.5,-1064.34 h60
  text ".plot_File_Name" at 577,-1064.34 h60
  text "GENERATED    :" at 2250,-1064.34 h60
  text ".Print_Date" at 3119.5,-1064.34 h60
  text ".Print_Time" at 3848.5,-1064.34 h60
  text "TEXAS INSTRUMENTS" at 5113,-1064.34 h60
M12 Stackup:
  drawing of 399 lines, arcs and shapes, not listed
  text "Layer" at 9821.59,7874.94 h60
  text "Name" at 10231.51,7874.94 h60
  text "Material" at 11561.12,7874.94 h60
  text "Thickness" at 12160.97,7874.94 h60
  text "Constant" at 12810.81,7874.94 h60
  text "Board Layer Stack" at 13380.67,7874.94 h60
  text "Top Overlay" at 10231.51,7754.94 h60
  text "Top Solder" at 10231.51,7634.94 h60
  text "SM-001" at 11561.12,7634.94 h60
  text "1.00mil" at 12160.97,7634.94 h60
  text "4" at 12810.81,7634.94 h60
  text "Top Surface Finish" at 10231.51,7514.94 h60
  text "PbSn" at 11561.12,7514.94 h60
  text "0.79mil" at 12160.97,7514.94 h60
  text "1" at 9821.59,7394.94 h60
  text "Top Layer" at 10231.51,7394.94 h60
  text "CF-004" at 11561.12,7394.94 h60
  text "1.38mil" at 12160.97,7394.94 h60
  text "Dielectric 1" at 10231.51,7274.94 h60
  text "PP-017" at 11561.12,7274.94 h60
  text "5.10mil" at 12160.97,7274.94 h60
  text "4.3" at 12810.81,7274.94 h60
  text "Dielectric 2" at 10231.51,7154.94 h60
  text "PP-017" at 11561.12,7154.94 h60
  text "5.10mil" at 12160.97,7154.94 h60
  text "4.3" at 12810.81,7154.94 h60
  text "2" at 9821.59,7034.94 h60
  text "Int1 (GND)" at 10231.51,7034.94 h60
  text "CF-004" at 11561.12,7034.94 h60
  text "1.38mil" at 12160.97,7034.94 h60
  text "Dielectric 3" at 10231.51,6914.94 h60
  text "Core-039" at 11561.12,6914.94 h60
  text "28.00mil" at 12160.97,6914.94 h60
  text "4.8" at 12810.81,6914.94 h60
  text "3" at 9821.59,6794.94 h60
  text "Int2 (PWR)" at 10231.51,6794.94 h60
  text "CF-004" at 11561.12,6794.94 h60
  text "1.38mil" at 12160.97,6794.94 h60
  text "Dielectric 4" at 10231.51,6674.94 h60
  text "PP-017" at 11561.12,6674.94 h60
  text "5.10mil" at 12160.97,6674.94 h60
  text "4.3" at 12810.81,6674.94 h60
  text "Dielectric 5" at 10231.51,6554.94 h60
  text "PP-017" at 11561.12,6554.94 h60
  text "5.10mil" at 12160.97,6554.94 h60
  text "4.3" at 12810.81,6554.94 h60
  text "4" at 9821.59,6434.94 h60
  text "Bottom Layer" at 10231.51,6434.94 h60
  text "CF-004" at 11561.12,6434.94 h60
  text "1.38mil" at 12160.97,6434.94 h60
  text "Bottom Surface Finish" at 10231.51,6314.94 h60
  text "PbSn" at 11561.12,6314.94 h60
  text "0.79mil" at 12160.97,6314.94 h60
  text "Bottom Solder" at 10231.51,6194.94 h60
  text "SM-001" at 11561.12,6194.94 h60
  text "1.00mil" at 12160.97,6194.94 h60
  text "4" at 12810.81,6194.94 h60
  text "Bottom Overlay" at 10231.51,6074.94 h60
  text ".Layer_Name" at 577,-858.49 h60
M13 Component Bodies Top:
  text ".Layer_Name" at 577,-858.49 h60
M14 Component Bodies Bottom:
  text ".Layer_Name" at 577,-858.49 h60
M15 Courtyards Top:
  text ".Layer_Name" at 577,-858.49 h60
M16 Courtyards Bottom:
  text ".Layer_Name" at 577,-858.49 h60
Drill Drawing:
  circle w10: c5363.72,3041.64 r27.63
  lines w10: 5336.09,2268.1 5391.34,2268.1 5391.34,2323.35 5336.09,2323.35 5336.09,2268.1 ; 5336.09,2392.42 5363.72,2406.23 5391.34,2392.42 5377.53,2420.04 5391.34,2447.67 5363.72,2433.86 5336.09,2447.67 5349.9,2420.04 5336.09,2392.42 ; 5336.09,2571.99 5391.34,2571.99 5363.72,2516.74 5336.09,2571.99 ; 5336.09,2668.68 5363.72,2641.06 5391.34,2668.68 5363.72,2696.31 5336.09,2668.68 ; 5336.09,2765.38 5391.34,2765.38 5391.34,2820.63 5336.09,2820.63 5336.09,2765.38 ; 5336.09,2889.7 5336.09,2903.51 5349.9,2917.32 5336.09,2931.14 5336.09,2944.95 5349.9,2944.95 5363.72,2931.14 5377.53,2944.95 5391.34,2944.95 5391.34,2931.14 5377.53,2917.32 5391.34,2903.51 5391.34,2889.7 5377.53,2889.7 5363.72,2903.51 5349.9,2889.7 5336.09,2889.7 ; 5336.09,3152.15 5349.9,3152.15 5349.9,3138.34 5377.53,3138.34 5377.53,3152.15 5391.34,3152.15 5391.34,3179.78 5377.53,3179.78 5377.53,3193.59 5349.9,3193.59 5349.9,3179.78 5336.09,3179.78 5336.09,3152.15 ; 5336.09,3276.47 5349.9,3276.47 5363.72,3262.66 5377.53,3276.47 5391.34,3276.47 5377.53,3290.28 5391.34,3304.1 5377.53,3304.1 5363.72,3317.91 5349.9,3304.1 5336.09,3304.1 5349.9,3290.28 5336.09,3276.47 ; 5347.14,2279.15 5380.29,2279.15 5380.29,2312.3 5347.14,2312.3 5347.14,2279.15
  lines w12: 5286,2230.8 8518.02,2230.8 ; 5286,3349.68 8518.02,3349.68 ; 5623.88,2106.48 5623.88,3474 ; 5955.99,2106.48 5955.99,3474 ; 6592.63,2106.48 6592.63,3474 ; 6851.84,2106.48 6851.84,3474 ; 7227.1,2106.48 7227.1,3474 ; 7951.43,2106.48 7951.43,3474 ; 5286,2106.48 8518.02,2106.48 8518.02,3474 5286,3474 5286,2106.48
  text "Symbol" at 5360.59,3386.98 h72
  text "Quantity" at 5661.17,3386.98 h72
  text "Finished Hole Size" at 5993.29,3386.98 h72
  text "Plated" at 6629.93,3386.98 h72
  text "Hole Type" at 6889.14,3386.98 h72
  text "Drill Layer Pair" at 7264.39,3386.98 h72
  text "Hole Tolerance" at 7988.72,3386.98 h72
  text "20" at 5661.17,3262.66 h60
  text "7.87mil (0.200mm)" at 5993.29,3262.66 h60
  text "PTH" at 6629.93,3262.66 h60
  text "Round" at 6889.14,3262.66 h60
  text "Top Layer - Bottom Layer" at 7264.39,3262.66 h60
  text "74" at 5661.17,3138.34 h60
  text "8.00mil (0.203mm)" at 5993.29,3138.34 h60
  text "PTH" at 6629.93,3138.34 h60
  text "Round" at 6889.14,3138.34 h60
  text "Top Layer - Bottom Layer" at 7264.39,3138.34 h60
  text "1" at 5661.17,3014.02 h60
  text "12.00mil (0.305mm)" at 5993.29,3014.02 h60
  text "PTH" at 6629.93,3014.02 h60
  text "Round" at 6889.14,3014.02 h60
  text "Top Layer - Bottom Layer" at 7264.39,3014.02 h60
  text "1" at 5661.17,2889.7 h60
  text "17.72mil (0.450mm)" at 5993.29,2889.7 h60
  text "PTH" at 6629.93,2889.7 h60
  text "Round" at 6889.14,2889.7 h60
  text "Top Layer - Bottom Layer" at 7264.39,2889.7 h60
  text "3" at 5661.17,2765.38 h60
  text "40.00mil (1.016mm)" at 5993.29,2765.38 h60
  text "PTH" at 6629.93,2765.38 h60
  text "Round" at 6889.14,2765.38 h60
  text "Top Layer - Bottom Layer" at 7264.39,2765.38 h60
  text "6" at 5661.17,2641.06 h60
  text "43.31mil (1.100mm)" at 5993.29,2641.06 h60
  text "PTH" at 6629.93,2641.06 h60
  text "Round" at 6889.14,2641.06 h60
  text "Top Layer - Bottom Layer" at 7264.39,2641.06 h60
  text "16" at 5661.17,2516.74 h60
  text "43.31mil (1.100mm)" at 5993.29,2516.74 h60
  text "PTH" at 6629.93,2516.74 h60
  text "Round" at 6889.14,2516.74 h60
  text "Top Layer - Bottom Layer" at 7264.39,2516.74 h60
  text "+/-5.91mil" at 7988.72,2516.74 h60
  text "11" at 5661.17,2392.42 h60
  text "45.28mil (1.150mm)" at 5993.29,2392.42 h60
  text "PTH" at 6629.93,2392.42 h60
  text "Round" at 6889.14,2392.42 h60
  text "Top Layer - Bottom Layer" at 7264.39,2392.42 h60
  text "2" at 5661.17,2268.1 h60
  text "51.18mil (1.300mm)" at 5993.29,2268.1 h60
  text "PTH" at 6629.93,2268.1 h60
  text "Round" at 6889.14,2268.1 h60
  text "Top Layer - Bottom Layer" at 7264.39,2268.1 h60
  text "134 Total" at 5661.17,2143.78 h60
  text ".Layer_Name" at 577,-858.49 h60
M17 Embedded Cavity:
  text ".Layer_Name" at 577,-858.49 h60
M18 Embedded Assembly:
  text ".Layer_Name" at 577,-858.49 h60
M19 Embedded Keepout:
  text ".Layer_Name" at 577,-858.49 h60

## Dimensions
0,-400 to 1000,-400 on M2 Board Dimensions
0,0 to 0,1181.1 on M2 Board Dimensions
0,0 to 2755.91,0 on M2 Board Dimensions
